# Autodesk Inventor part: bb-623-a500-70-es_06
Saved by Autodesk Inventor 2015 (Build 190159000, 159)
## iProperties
Created: 2022-04
Part Number: bb-623-a500-70-es_06
Checked By: TraceParts S.A.
Material: Generic
Catalog Web Link: www.traceparts.com
Document SubType Name: Modeling
Designer: TraceParts
Density: 1 g/cm^3
Appearance: Default
Company: TraceParts S.A.
Author: TraceParts
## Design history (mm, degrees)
feature "bb-623-a500-70-es_06.ipt"
body "Solid1"
